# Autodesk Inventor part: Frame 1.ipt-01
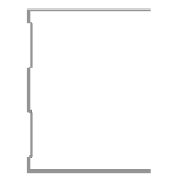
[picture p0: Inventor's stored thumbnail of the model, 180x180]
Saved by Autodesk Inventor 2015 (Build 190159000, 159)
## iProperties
Created: 2015-04
Part Number: Frame 1.ipt-01
Material: Aluminum 6061
Document SubType Name: Modeling
Standard: Unnamed
Designer: suporte
Language: en-US
Size Designation: (Unnamed 1)
Categories: <MemberInstance><Categories><Category DisplayName="Structural Shapes" InternalName="089c4875-fa83-4c05-b084-43b9cc11f5ed" Mnemonic="GRDR"><CategoryParameter Dis
Density: 2.7 g/cm^3
Appearance: Aluminum - Flat
IsCustomPart: 1
_CCFamilyMember: 1
_CCFamilyDisplayName: Frame 1
_FrameMemberDoc: Frame Member File
_Version: 15.0.0
_GetPNFromCC: 1
Author: suporte
G_L: 518,599 mm
G_W: 70,000 mm
G_H: 75,000 mm
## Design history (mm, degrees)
node "Start Plane"
node "End Plane"
sketch "Sketch"
  geometry: L1 (34.6, 37.5)-(34.6, 36.7); L2 (34.6, 36.7)-(-34.6, 36.7); L3 (-34.6, -36.7)-(34.6, -36.7); L4 (34.6, -36.7)-(34.6, -37.5); L5 (34.6, -37.5)-(-35.4, -37.5); L6 (-35.4, 37.5)-(34.6, 37.5); L7 (-34.6, 36.7)-(-34.6, 31.7); L8 (-34.6, 31.7)-(-33.4, 30.5); L9 (-33.4, 30.5)-(-33.4, 10.746); L10 (-33.4, 10.746)-(-34.6, 9.546); L11 (-34.6, 9.546)-(-34.6, -9.546); L12 (-34.6, -9.546)-(-33.4, -10.746); L13 (-33.4, -10.746)-(-33.4, -30.5); L14 (-33.4, -30.5)-(-34.6, -31.7); L15 (-34.6, -31.7)-(-34.6, -36.7); L16 (-35.4, -37.5)-(-35.4, -31.369); L17 (-35.4, -31.369)-(-34.2, -30.169); L18 (-34.2, -30.169)-(-34.2, -11.077); L19 (-34.2, -11.077)-(-35.4, -9.877); L20 (-35.4, -9.877)-(-35.4, 9.877); L21 (-35.4, 9.877)-(-34.2, 11.077); L22 (-34.2, 11.077)-(-34.2, 30.169); L23 (-34.2, 30.169)-(-35.4, 31.369); L24 (-35.4, 31.369)-(-35.4, 37.5); L25 (-35.4, 0)-(30.37, 0); 3 further points
  constraints: 50 end point, 10 point on line, 9 parallel, 5 perpendicular, 4 equal length, 3 midpoint, 3 vertical, 2 vertical alignment, 1 collinear, 1 horizontal, 1 horizontal alignment
  dimensions: "d3" = 0.8 distance of L1.start L1.end; "d5" = 75 distance between parallel lines of L5 L6; "d6" = 0.8 distance between parallel lines of L24 L7; "d7" = 0.8 distance between parallel lines of L8 L23; "d8" = 0.8 distance between parallel lines of L22 L9; "d9" = 0.8 distance between parallel lines of L17 L14; "d10" = 0.8 distance between parallel lines of L13 L18; "d11" = 0.8 distance between parallel lines of L12 L19; "d12" = 0.8 distance between parallel lines of L21 L10; "d13" = 5 distance of L2.end L7.end; "d15" = 135 deg angle of L9 L8; "d16" = 2 distance between parallel lines of L24 L9; "d17" = 70 distance of L6.start L1.start
extrude "Body" join sketch "Sketch" stored distance "d24" = 0.13; taper "d25" = 0 deg
node "Driven Length"
  sketch "Sketch8"
    geometry: L1 (0, 0)-(10, 0) reference
    constraints: 2 end point, 1 horizontal
  workplane "Work Plane6"
  sketch "Sketch9"
    geometry: L1 (-2, 0)-(12, 0) reference; L2 (-2, 518.599)-(12, 518.599) reference
    dimensions: "d27" = 518.59902 distance between parallel lines of L1 L2 (derived)
body "Solid1"
other parameters: "tamanho" = 518.59902, "G_OFFSET_START" = 0 [user parameter; used in 1 equation term], "G_OFFSET_END" = 0 [user parameter; used in 1 equation term], "d22" = 0 (computed from G_OFFSET_START), "d23" = 518.59902 (= tamanho + G_OFFSET_END), "G_L" = 518.59902 (= d27) [user parameter], "d32" = 90 deg
